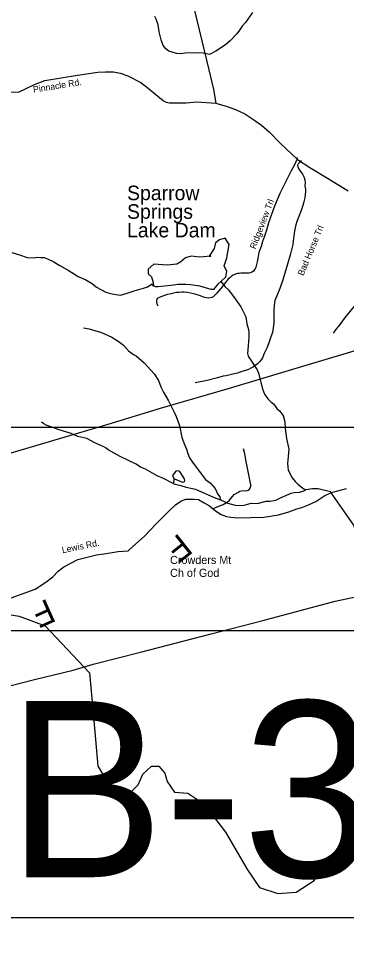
# Model space of a CAD drawing. Extents: x 1268485 to 1426702, y 514839 to 616766.
# Drawn here: x 1313407 to 1316736, y 524572 to 533949 of the extents above; entities that cross this region are included whole.
import ezdxf

# ---------------------------------------------------------------- set-up
doc = ezdxf.new("R2010")
doc.units = 0
for name, color, linetype in [('Old_Level_10', 7, 'Continuous'), ('Old_Level_11', 7, 'Continuous'), ('Old_Level_21', 7, 'Continuous'), ('Old_Level_22', 7, 'Continuous'), ('Old_Level_3', 7, 'Continuous'), ('Old_Level_32', 7, 'Continuous'), ('Old_Level_35', 7, 'Continuous'), ('Old_Level_56', 7, 'Continuous'), ('Old_Level_58', 7, 'Continuous'), ('Old_Level_59', 7, 'Continuous'), ('Old_Level_60', 7, 'Continuous'), ('Old_Level_62', 7, 'Continuous'), ('Old_Level_63', 7, 'Continuous')]:
    doc.layers.add(name, color=color, linetype=linetype)

msp = doc.modelspace()

# ---------------------------------------------------------------- linework, layer by layer
at = {"layer": 'Old_Level_21'}
msp.add_line((1314508.448, 532252.896), (1314508.448, 532252.896), dxfattribs=at)
at = {"layer": 'Old_Level_22'}
msp.add_line((1314945.164, 528495.604), (1314945.164, 528495.604), dxfattribs=at)
at = {"layer": 'Old_Level_3'}
msp.add_lwpolyline([(1319379.596, 524821.535), (1312543.078, 524821.535), (1312543.078, 527740.136), (1319379.596, 527740.136), (1319379.596, 524821.535)], dxfattribs=at)
at = {"layer": 'Old_Level_32'}
for points in [[(1314926.29, 535195.055), (1314932.615, 535004.83), (1314935.777, 534875.967), (1314957.914, 534771.651), (1315081.247, 534431.086), (1315144.496, 534228.588), (1315340.194, 533427.953), (1315386.557, 533228.58), (1315409.738, 533091.575)], [(1313266.571, 533204.848), (1313406.572, 533201.43), (1313568.463, 533279.954), (1313672.688, 533320.924), (1314004.975, 533375.678), (1314211.667, 533404.934), (1314289.791, 533409.164), (1314371.83, 533409.113), (1314437.55, 533393.584), (1314517.029, 533365.772), (1314647.544, 533298.713), (1314722.26, 533242.983), (1314877.324, 533113.201), (1314905.045, 533098.636), (1314940.963, 533093.711), (1314994.964, 533092.424), (1315107.05, 533093.97), (1315215.294, 533103.397), (1315409.738, 533091.575)], [(1315409.738, 533091.575), (1315525.647, 533055.79), (1315609.944, 533025.117), (1315702.67, 532982.175), (1315803.826, 532915.717), (1315873.37, 532866.641), (1315951.345, 532799.16), (1316063.038, 532684.649), (1316237.954, 532517.993), (1316362.291, 532436.199), (1316543.53, 532329.867), (1316754.272, 532201.041)], [(1313258.435, 528042.096), (1313577.342, 528158.737), (1313682.994, 528228.245), (1313756.365, 528284.597), (1313809.733, 528341.35), (1313866.662, 528386.027), (1314010.598, 528458.767), (1314091.085, 528480.959), (1314199.65, 528506.387), (1314298.177, 528520.212), (1314418.663, 528541.398), (1314520.826, 528546.945), (1314566.89, 528590.929), (1314686.61, 528694.391), (1314803.609, 528819.635), (1314928.772, 528947.602), (1315004.957, 529018.391), (1315062.096, 529053.787), (1315105.631, 529072.845), (1315187.259, 529072.845), (1315233.514, 529067.4), (1315290.653, 529034.727), (1315343.996, 529002.008), (1315404.831, 528952.56), (1315463.907, 528915.153), (1315517.55, 528896.065), (1315561.429, 528888.978), (1315631.351, 528883.369), (1315895.561, 528887.256), (1316046.835, 528912.126), (1316150.128, 528942.134), (1316233.429, 528972.143), (1316283.409, 528985.48), (1316351.81, 529012.946), (1316423.354, 529048.831), (1316486.662, 529088.842), (1316516.651, 529108.848), (1316564.041, 529130.022), (1316596.692, 529143.635), (1316736.564, 529178.868)]]:
    msp.add_lwpolyline(points, dxfattribs=at)
at = {"layer": 'Old_Level_35'}
for points in [[(1316235.988, 532539.126), (1316230.041, 532512.111), (1316222.967, 532493.041), (1316202.872, 532451.979), (1316175.907, 532403.894), (1316105.78, 532266.611), (1316059.643, 532172.442), (1316004.484, 532046.18), (1315944.404, 531874.859), (1315923.386, 531800.733), (1315902.368, 531739.628), (1315883.298, 531685.494), (1315868.227, 531636.436), (1315855.206, 531601.372), (1315847.209, 531574.305), (1315842.288, 531554.261), (1315836.239, 531513.199), (1315829.267, 531481.109), (1315823.115, 531453.067), (1315815.118, 531427.026), (1315806.096, 531400.984), (1315793.075, 531385.913), (1315776.158, 531374.943), (1315759.959, 531368.945), (1315743.042, 531364.947), (1315719.974, 531363.921), (1315688.909, 531363.921), (1315664.918, 531364.947), (1315645.848, 531362.947), (1315630.879, 531360.896), (1315616.73, 531357.872), (1315601.762, 531351.874), (1315586.793, 531342.852), (1315569.773, 531332.856), (1315550.601, 531317.835), (1315531.634, 531300.816), (1315515.64, 531281.746), (1315495.545, 531254.679), (1315472.476, 531225.614), (1315455.457, 531204.647), (1315437.515, 531182.553), (1315416.394, 531159.484), (1315398.35, 531140.517), (1315382.356, 531125.446), (1315368.412, 531117.449), (1315351.29, 531113.45), (1315331.298, 531110.425), (1315310.28, 531113.45), (1315286.084, 531122.421), (1315255.121, 531134.519), (1315210.01, 531147.489), (1315182.533, 531155.999), (1315150.852, 531162.509), (1315120.914, 531167.584), (1315088.721, 531170.557), (1315065.755, 531170.557), (1315036.638, 531168.558), (1315010.596, 531167.584), (1314981.581, 531162.509), (1314955.54, 531156.511), (1314919.451, 531147.489), (1314888.385, 531138.517), (1314860.396, 531128.419), (1314833.226, 531117.449), (1314815.284, 531106.427), (1314808.21, 531088.382), (1314808.21, 531070.389), (1314813.234, 531047.321), (1314821.231, 531033.275)], [(1316274.742, 532509.701), (1316269.104, 532493.861), (1316255.673, 532484.889), (1316245.42, 532474.739), (1316239.781, 532460.078), (1316242.037, 532445.366), (1316252.289, 532421.683), (1316271.359, 532392.36), (1316289.404, 532370.932), (1316300.784, 532350.632), (1316306.423, 532334.894), (1316311.959, 532312.338), (1316315.343, 532284.041), (1316314.215, 532252.515), (1316318.111, 532218.066), (1316318.726, 532193.818), (1316317.598, 532164.496), (1316313.087, 532128.458), (1316303.04, 532087.806), (1316292.787, 532050.538), (1316275.87, 532002.043), (1316252.289, 531938.887), (1316233.014, 531889.265), (1316222.864, 531854.303), (1316213.842, 531824.929), (1316207.075, 531792.275), (1316200.206, 531744.856), (1316194.67, 531688.416), (1316190.158, 531656.889), (1316182.264, 531613.982), (1316168.731, 531562.104), (1316129.258, 531433.485), (1316085.274, 531286.873), (1316058.105, 531210.183), (1316027.757, 531135.698), (1316009.61, 531087.204), (1316005.099, 531062.392), (1315999.46, 531000.364), (1315998.332, 530940.54), (1315998.332, 530855.956), (1315992.796, 530809.666), (1315983.774, 530762.299), (1315969.01, 530719.443), (1315949.837, 530667.564), (1315929.64, 530608.868), (1315901.343, 530548.019), (1315882.17, 530506.239), (1315869.765, 530483.684), (1315852.848, 530463.383), (1315833.675, 530444.211), (1315809.992, 530427.294), (1315790.922, 530412.633), (1315764.88, 530399.049), (1315739.967, 530387.822), (1315710.747, 530376.493), (1315674.658, 530365.266), (1315630.674, 530351.682), (1315581.051, 530339.327), (1315526.918, 530326.87), (1315516.05, 530324.615)], [(1317194.709, 531705.641), (1317181.79, 531676.061), (1317167.027, 531660.272), (1317150.11, 531636.538), (1317131.04, 531594.81), (1317107.254, 531541.804), (1317094.848, 531506.894), (1317075.676, 531450.453), (1317049.737, 531392.936), (1317028.206, 531347.825), (1316998.986, 531285.745), (1316969.664, 531228.177), (1316922.297, 531160.51), (1316871.547, 531097.354), (1316816.285, 531034.198), (1316721.551, 530916.856), (1316667.417, 530844.678), (1316624.459, 530788.238), (1316599.647, 530754.455)], [(1315516.05, 530324.615), (1315483.959, 530317.899), (1315425.417, 530304.315), (1315320.328, 530277.248), (1315200.885, 530252.437)], [(1315374.871, 528974.449), (1315423.264, 528994.545), (1315485.087, 529016.895), (1315525.175, 529041.399), (1315549.576, 529060.827), (1315577.975, 529098.711), (1315596.328, 529119.831), (1315632.622, 529139.311), (1315654.665, 529153.255), (1315670.659, 529157.458), (1315695.88, 529158.329), (1315720.282, 529156.638), (1315738.839, 529162.482), (1315752.27, 529171.76), (1315757.396, 529181.86), (1315762.42, 529192.01), (1315764.88, 529203.749), (1315764.88, 529218.051), (1315745.503, 529318.27), (1315716.898, 529452.169), (1315704.288, 529531.319), (1315691.574, 529581.865)]]:
    msp.add_lwpolyline(points, dxfattribs=at)
at = {"layer": 'Old_Level_56'}
for points in [[(1323366.294, 532177.376), (1322870.978, 532044.675), (1322166.251, 531856.96), (1321411.081, 531658.454), (1320883.684, 531522.597), (1320491.102, 531423.847), (1319838.818, 531256.887), (1319440.632, 531168.053), (1318922.163, 531078.039), (1318268.965, 530955.12), (1317830.82, 530869.291), (1317691.971, 530840.471), (1317442.112, 530764.26), (1316936.195, 530611.963), (1316289.347, 530416.88), (1315543.694, 530194.172)], [(1315543.694, 530194.172), (1314844.684, 529992.335), (1314314.563, 529830.521), (1313661.754, 529637.559), (1313176.2, 529492.857), (1312708.604, 529355.597), (1312468.827, 529283.185), (1312231.449, 529230.535), (1311774.779, 529129.072), (1311288.03, 529024.413), (1310746.877, 528901.04), (1310236.246, 528792.859), (1309868.059, 528713.228), (1309342.944, 528591.332), (1308906.316, 528491.467), (1308582.495, 528418.946), (1308035.3, 528293.694), (1307437.82, 528155.446), (1306972.988, 528046.144), (1306502.28, 527943.164), (1305969.204, 527823.43), (1305074.349, 527616.139)], [(1313211.665, 527150.601), (1313569.892, 527242.44), (1313962.359, 527335.389), (1314163.891, 527396.565), (1314644.966, 527517.546), (1315361.656, 527703.019), (1315887.094, 527840.916), (1316620.183, 528035.863), (1316843.479, 528084.795)]]:
    msp.add_lwpolyline(points, dxfattribs=at)
at = {"layer": 'Old_Level_58'}
msp.add_line((1315435.825, 531257.059), (1315435.825, 531257.059), dxfattribs=at)
at = {"layer": 'Old_Level_59'}
for points in [[(1313340.55, 531576.099), (1313416.111, 531552.415), (1313493.519, 531522.99), (1313561.493, 531520.786), (1313597.582, 531525.81), (1313631.621, 531525.143), (1313667.505, 531522.785), (1313701.236, 531511.405), (1313764.7, 531480.596), (1313819.859, 531445.019), (1313910.8, 531396.422), (1314011.275, 531330.395), (1314088.58, 531296.818), (1314153.684, 531261.036), (1314198.795, 531222.384), (1314293.734, 531173.684), (1314341.409, 531158.818), (1314393.185, 531147.079), (1314441.064, 531142.003), (1314509.552, 531161.176), (1314580.295, 531185.167), (1314676.874, 531211.158), (1314715.219, 531225.972), (1314763.919, 531256.987)], [(1315460.891, 531279.081), (1315503.644, 531227.305), (1315539.016, 531194.599), (1315606.888, 531102.993), (1315663.072, 531022.253), (1315712.695, 530922.752), (1315725.1, 530851.957), (1315739.762, 530794.235), (1315742.94, 530759.684), (1315745.913, 530713.65), (1315732.892, 530585.902), (1315731.97, 530548.173), (1315739.454, 530521.772), (1315828.344, 530385.413), (1315843.518, 530351.477), (1315881.863, 530192.305), (1315904.521, 530136.069), (1315937.534, 530091.061), (1315968.805, 530058.457), (1315994.334, 530037.388), (1316029.193, 529990.738), (1316054.619, 529966.44), (1316091.528, 529918.919), (1316110.188, 529856.994), (1316114.597, 529788.814), (1316128.233, 529685.928), (1316151.711, 529579.609), (1316139.1, 529468.266), (1316138.28, 529432.177), (1316142.791, 529363.997), (1316182.982, 529288.487), (1316214.15, 529251.731), (1316245.42, 529219.127), (1316302.424, 529176.118), (1316322.212, 529167.506)], [(1317010.914, 528347.352), (1316865.292, 528639.599), (1316811.261, 528808.101), (1316573.799, 529144.39), (1316448.425, 529176.557), (1316390.561, 529176.557), (1316322.212, 529167.506)], [(1313271.502, 527909.206), (1313412.949, 527883.474), (1313676.555, 527786.979), (1314126.659, 527308.669), (1314163.677, 526901.625), (1314213.034, 526362.888), (1314373.444, 526099.506), (1314546.193, 526099.506), (1314620.228, 526171.337), (1314669.585, 526279.085), (1314755.959, 526362.888), (1314829.995, 526362.888), (1314891.691, 526291.057), (1314916.369, 526207.254), (1314990.404, 526099.506), (1315126.136, 526087.534), (1315286.546, 525979.787), (1315508.651, 525692.461), (1315730.757, 525309.36), (1315854.149, 525129.781), (1316039.238, 525069.921), (1316224.326, 525081.893), (1316409.413, 525201.612), (1316668.537, 525524.854), (1317026.374, 525919.927)]]:
    msp.add_lwpolyline(points, dxfattribs=at)
at = {"layer": 'Old_Level_60'}
for points in [[(1315460.891, 531279.081), (1315511.752, 531326.684), (1315519.789, 531382.972), (1315495.678, 531439.262), (1315519.789, 531519.675), (1315543.899, 531656.376), (1315503.715, 531720.706), (1315447.458, 531704.624), (1315407.275, 531672.458), (1315391.201, 531616.17), (1315342.981, 531535.757), (1315359.054, 531535.757), (1315246.539, 531527.715), (1315158.135, 531535.757), (1315101.878, 531519.675), (1315053.657, 531479.468), (1315013.474, 531455.344), (1314917.033, 531447.303), (1314780.408, 531455.344), (1314724.151, 531407.096), (1314724.151, 531358.849), (1314756.298, 531326.684), (1314772.372, 531270.395), (1314775.402, 531232.944)], [(1315460.891, 531279.081), (1315430.235, 531251.758), (1315384.919, 531200.187), (1315361.03, 531200.648), (1315245.689, 531233.354), (1315151.877, 531245.914), (1315103.998, 531249.297), (1315023.925, 531248.477), (1314983.735, 531241.915), (1314951.644, 531240.89), (1314825.332, 531225.357), (1314801.341, 531225.87), (1314775.402, 531232.944), (1314765.662, 531244.632), (1314763.919, 531256.987)]]:
    msp.add_lwpolyline(points, dxfattribs=at)
at = {"layer": 'Old_Level_62'}
msp.add_line((1314984.862, 529226.407), (1314985.99, 529276.439), dxfattribs=at)
for points in [[(1315780.567, 534011.041), (1315710.132, 533908.258), (1315675.273, 533872.836), (1315648.308, 533829.878), (1315621.549, 533794.301), (1315553.882, 533724.276), (1315510.923, 533686.597), (1315468.17, 533656.249), (1315411.268, 533618.827), (1315346.472, 533584.84), (1315282.7, 533595.964), (1315230.72, 533599.502), (1315098.564, 533596.374), (1315050.479, 533591.607), (1315010.391, 533592.427), (1314932.984, 533618.622), (1314901.611, 533643.024), (1314876.185, 533673.884), (1314853.629, 533734.272), (1314835.379, 533812.602), (1314825.024, 533883.345), (1314804.519, 533943.682), (1314789.038, 533970.236)], [(1315460.891, 531279.081), (1315511.752, 531326.684), (1315519.789, 531382.972), (1315495.678, 531439.262), (1315519.789, 531519.675), (1315543.899, 531656.376), (1315503.715, 531720.706), (1315447.458, 531704.624), (1315407.275, 531672.458), (1315391.201, 531616.17), (1315342.981, 531535.757), (1315359.054, 531535.757), (1315246.539, 531527.715), (1315158.135, 531535.757), (1315101.878, 531519.675), (1315053.657, 531479.468), (1315013.474, 531455.344), (1314917.033, 531447.303), (1314780.408, 531455.344), (1314724.151, 531407.096), (1314724.151, 531358.849), (1314756.298, 531326.684), (1314772.372, 531270.395), (1314775.402, 531232.944)], [(1315460.891, 531279.081), (1315430.235, 531251.758), (1315384.919, 531200.187), (1315361.03, 531200.648), (1315245.689, 531233.354), (1315151.877, 531245.914), (1315103.998, 531249.297), (1315023.925, 531248.477), (1314983.735, 531241.915), (1314951.644, 531240.89), (1314825.332, 531225.357), (1314801.341, 531225.87), (1314775.402, 531232.944), (1314765.662, 531244.632), (1314763.919, 531256.987)], [(1314065.204, 530810.691), (1314123.028, 530799.669), (1314250.161, 530762.657), (1314353.097, 530713.804), (1314418.303, 530676.382), (1314471.309, 530635.115), (1314524.008, 530575.752), (1314575.168, 530538.638), (1314600.8, 530526.642), (1314683.333, 530456.053), (1314782.681, 530344.095), (1314829.125, 530275.043), (1314851.784, 530210.554), (1314880.286, 530151.704), (1314928.473, 530068.71), (1314987.836, 529952.599), (1315006.803, 529908.718), (1315040.636, 529817.777), (1315063.91, 529696.694), (1315090.259, 529626.413), (1315113.122, 529577.558), (1315124.093, 529535.472), (1315143.163, 529490.771), (1315179.867, 529435.867), (1315304.026, 529269.263), (1315355.186, 529233.738), (1315404.091, 529181.039), (1315426.75, 529126.444), (1315450.023, 529093.995), (1315455.354, 529063.493)], [(1314984.862, 529226.407), (1314880.081, 529279.413), (1314812.619, 529308.684), (1314696.149, 529375.019), (1314646.629, 529396.549), (1314601.312, 529425.359), (1314439.014, 529505.739), (1314318.443, 529570.536), (1314296.913, 529589.041), (1314273.332, 529603.447), (1314182.083, 529643.842), (1314099.037, 529687.364), (1314009.532, 529707.254), (1313942.172, 529737.294), (1313818.936, 529775.896), (1313688.01, 529822.852), (1313664.327, 529835.617), (1313638.695, 529854.225)], [(1314985.99, 529276.439), (1315005.983, 529271.98), (1315071.394, 529244.401), (1315089.439, 529248.142), (1315095.693, 529260.292), (1315090.157, 529278.49), (1315043.815, 529351.643), (1315027.923, 529359.332), (1315003.932, 529356.512), (1314970.919, 529312.888), (1314972.662, 529301.353), (1314985.99, 529276.439)], [(1314984.862, 529226.407), (1315054.478, 529211.08), (1315108.099, 529193.598), (1315201.705, 529171.197), (1315391.891, 529086.921), (1315455.354, 529063.493)], [(1315455.354, 529063.493), (1315532.556, 529029.967), (1315606.273, 529012.076), (1315658.151, 529008.539), (1315698.239, 529010.179), (1315766.726, 529030.172), (1315830.702, 529028.891), (1315919.285, 529050.882), (1315957.322, 529051.754), (1316017.505, 529060.417), (1316072.254, 529089.637), (1316173.344, 529132.75), (1316205.537, 529140.337), (1316259.569, 529140.9), (1316295.863, 529152.435), (1316322.212, 529167.506)]]:
    msp.add_lwpolyline(points, dxfattribs=at)
at = {"layer": 'Old_Level_63'}
for points in [[(1305516.95, 558564.883), (1305516.95, 529802.059), (1368033.021, 529802.059), (1368033.021, 573241.255), (1305516.95, 573241.255), (1305516.95, 558564.883)], [(1305516.95, 529802.059), (1368033.021, 529802.059), (1368033.021, 517504.204), (1305516.95, 517504.204), (1305516.95, 529802.059)]]:
    msp.add_lwpolyline(points, dxfattribs=at)

# ---------------------------------------------------------------- texts
at = {"layer": 'Old_Level_10'}
for s, rotation, p in [('Ridgeview Trl', 69.1197806, (1315812.324, 531603.817)), ('Bad Horse Trl', 67.2973, (1316297.792, 531333.084))]:
    msp.add_text(s, height=65.61666, rotation=rotation, dxfattribs=at).set_placement(p)
at = {"layer": 'Old_Level_11'}
for s, height, rotation, p in [('Pinnacle Rd.', 65.61666, 9.3570444, (1313560.639, 533194.191)), ('Lewis Rd.', 65.6167, 11.6297861, (1313854.317, 528521.391))]:
    msp.add_text(s, height=height, rotation=rotation, dxfattribs=at).set_placement(p)
at = {"layer": 'Old_Level_21'}
for s, p in [('Sparrow', (1314508.448, 532105.258)), ('Springs', (1314508.448, 531916.611)), ('Lake Dam', (1314508.448, 531727.963))]:
    msp.add_text(s, height=147.6375, dxfattribs=at).set_placement(p)
at = {"layer": 'Old_Level_22'}
for rotation, p in [(218.3784778, (1315039.124, 528732.959)), (204.2038778, (1313701.72, 528065.996))]:
    msp.add_text('F', height=246.062, rotation=rotation, dxfattribs=at).set_placement(p)
for s, height, p in [('Crowders Mt', 82.02083, (1314945.164, 528413.584)), ('Ch of God', 82.0208, (1314945.164, 528282.35))]:
    msp.add_text(s, height=height, dxfattribs=at).set_placement(p)
at = {"layer": 'Old_Level_3'}
msp.add_text('B-3840', height=1788.0542, dxfattribs=at).set_placement((1313290.241, 525234.563))

doc.saveas('drawing.dxf')
